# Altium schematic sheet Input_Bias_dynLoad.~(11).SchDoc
size 431 x 279 mm; Date: Not shown in title block; ApprovedBy: Not shown in title block; CheckedBy: Not shown in title block; Author: Not shown in title block; CompanyName: Not shown in title block; Engineer: Not shown in title block; Organization: Not shown in title block; Address1: Not shown in title block; Address2: Not shown in title block; Address3: Not shown in title block; Address4: Not shown in title block; DocumentNumber: 2; Revision: Use project parameter SCH_Rev; SheetNumber: 2; SheetTotal: 5; PageSetup: Record=PageOptions|CenterHorizontal=True|CenterVertical=True|PrintScale=1.00|XCorrection=1.00|YCorrection=1.00|PrintKind=0|BorderSize=5000000|LeftOffset=0|BottomOffset=0|Orientation=2|PaperLength=1000|PaperWidth=1000|Scale=100|PaperSource=15|PrintQuality=600|MediaType=1|DitherType=10|PaperKind=Letter|PrintScaleMode=1
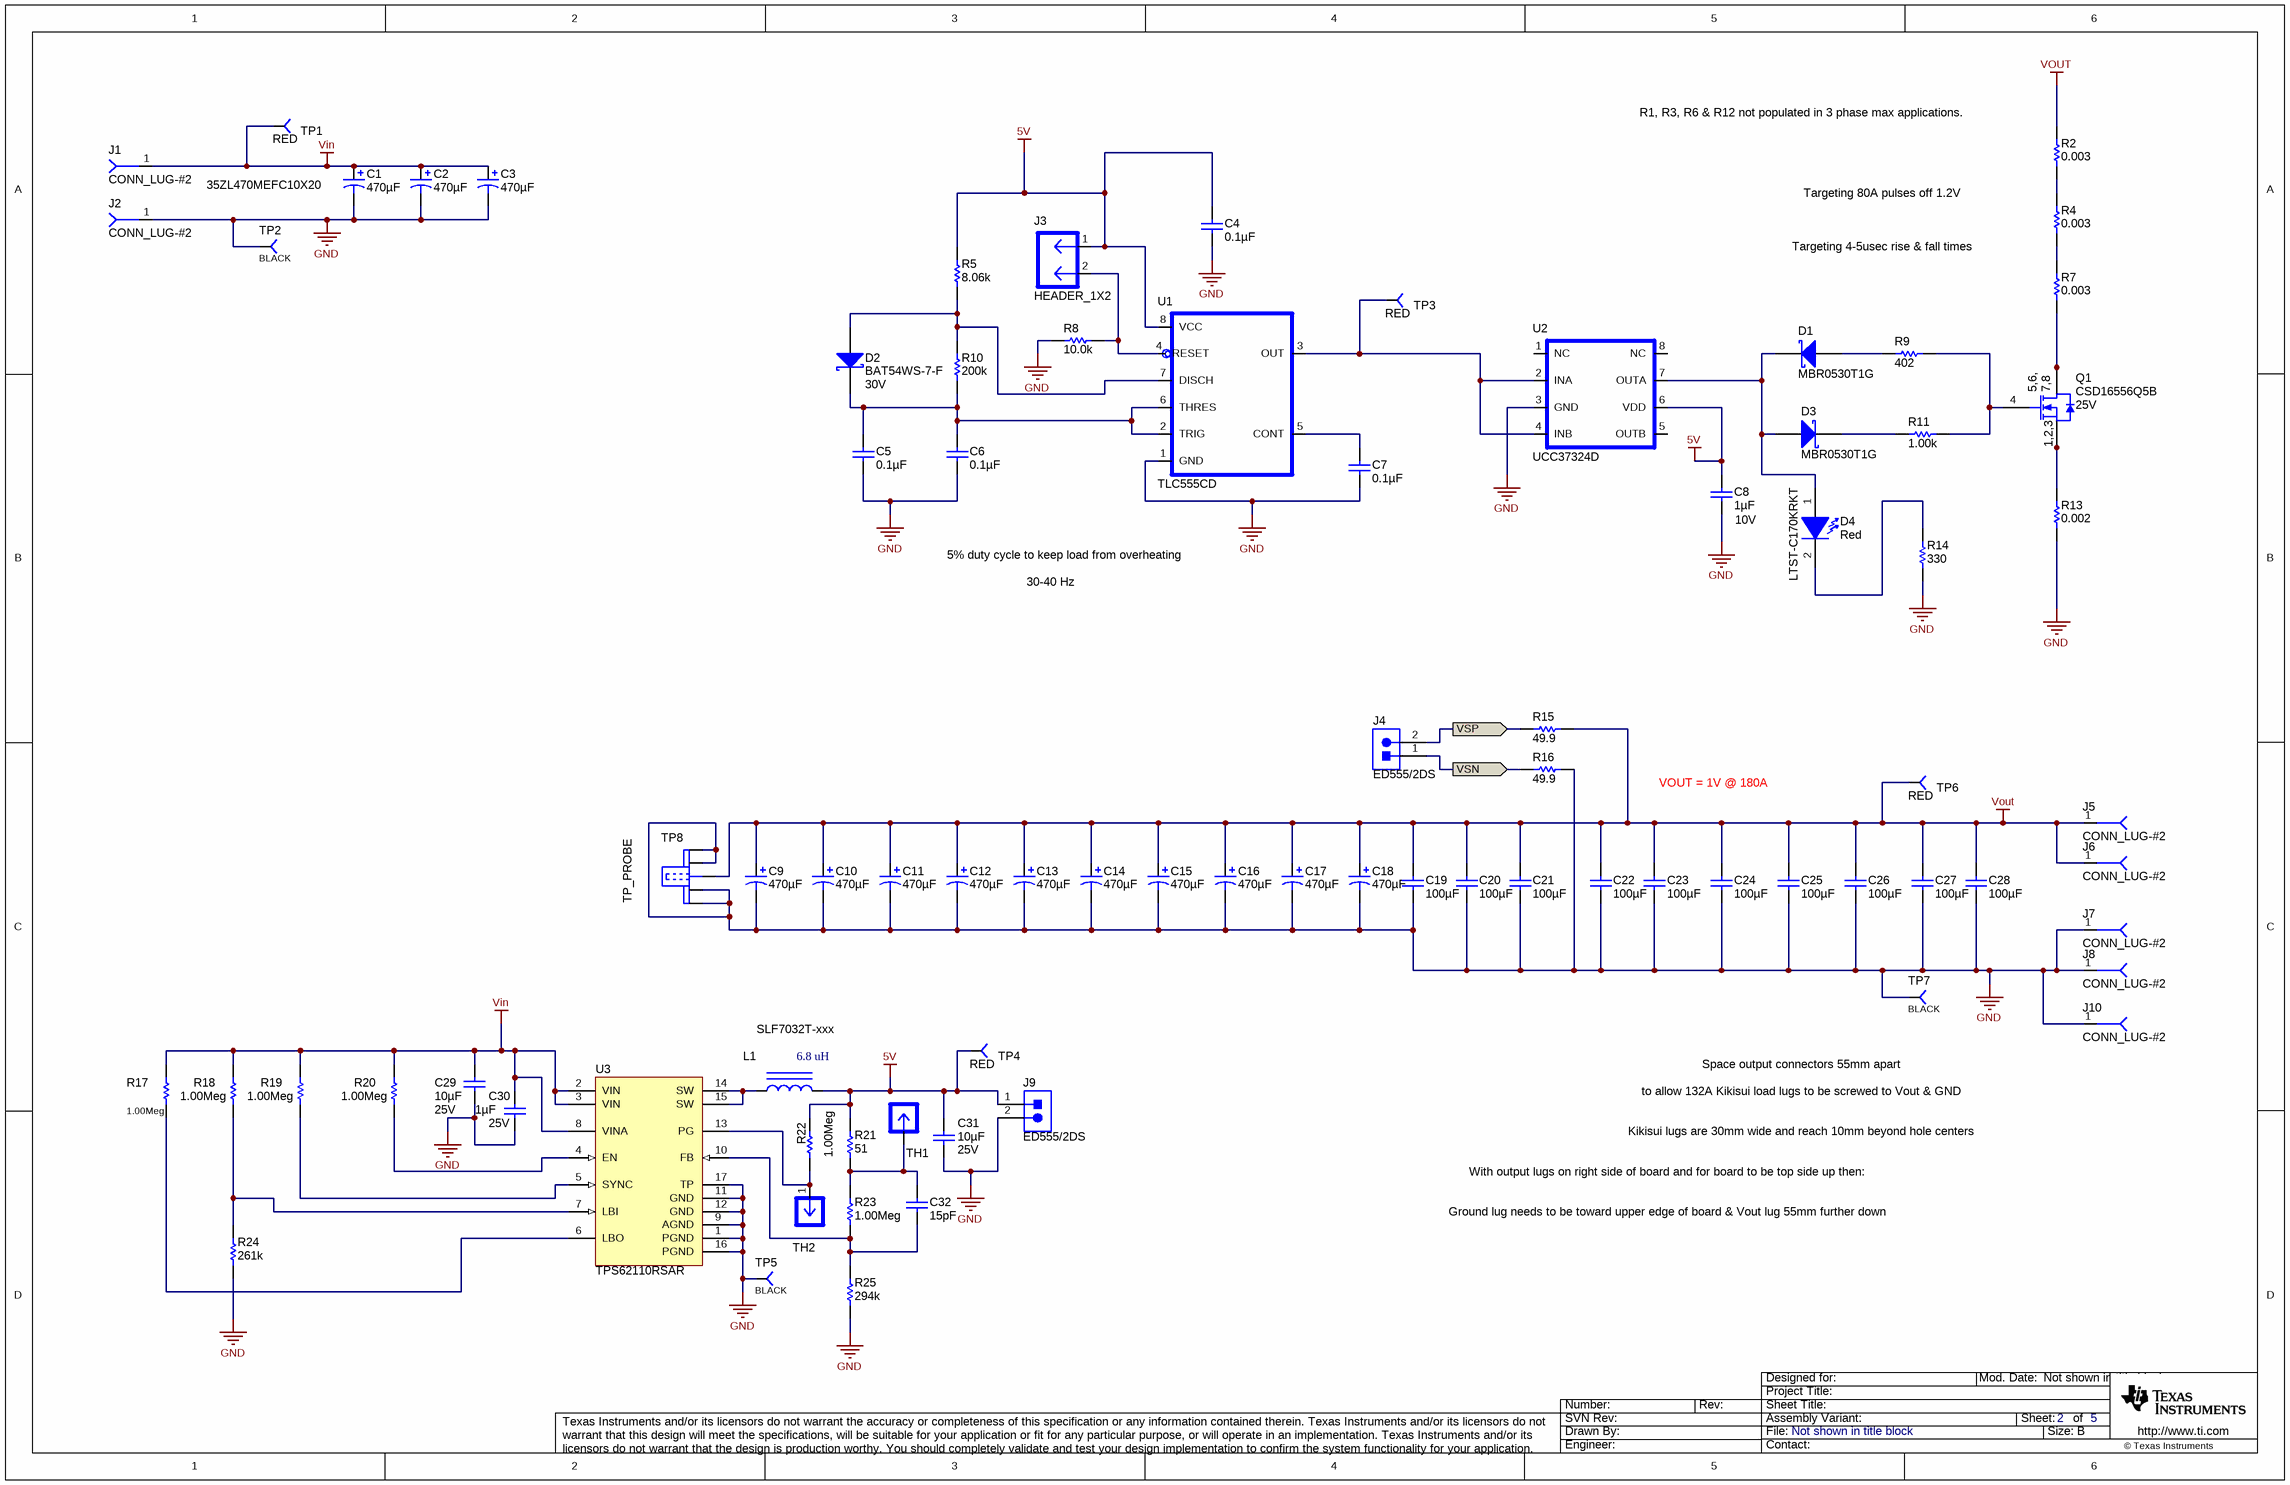
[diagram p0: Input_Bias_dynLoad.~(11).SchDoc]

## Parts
C1  ValueDisplayed: 470µF  [CAPPR5-10X20]  (hidden comment: 35ZL470MEFC10X20)
C2  ValueDisplayed: 470µF  [CAPPR5-10X20]  (hidden comment: 35ZL470MEFC10X20)
C3  ValueDisplayed: 470µF  [CAPPR5-10X20]  (hidden comment: 35ZL470MEFC10X20)
C4  ValueDisplayed: 0.1µF  [0402]  (hidden comment: C1005X7R1H104M)
C5  ValueDisplayed: 0.1µF  [0402]  (hidden comment: C1005X7R1H104M)
C6  ValueDisplayed: 0.1µF  [0402]  (hidden comment: C1005X7R1H104M)
C7  ValueDisplayed: 0.1µF  [0402]  (hidden comment: C1005X7R1H104M)
C8  ValueDisplayed: 1µF  Value2: 10V  [0402]  (hidden comment: GRM155R61A105KE15D)
C9  ValueDisplayed: 470µF  [CAPAE_SP-Cap_Standard]  (hidden comment: EEFSX0E471ER)
C10  ValueDisplayed: 470µF  [CAPAE_SP-Cap_Standard]  (hidden comment: EEFSX0E471ER)
C11  ValueDisplayed: 470µF  [CAPAE_SP-Cap_Standard]  (hidden comment: EEFSX0E471ER)
C12  ValueDisplayed: 470µF  [CAPAE_SP-Cap_Standard]  (hidden comment: EEFSX0E471ER)
C13  ValueDisplayed: 470µF  [CAPAE_SP-Cap_Standard]  (hidden comment: EEFSX0E471ER)
C14  ValueDisplayed: 470µF  [CAPAE_SP-Cap_Standard]  (hidden comment: EEFSX0E471ER)
C15  ValueDisplayed: 470µF  [CAPAE_SP-Cap_Standard]  (hidden comment: EEFSX0E471ER)
C16  ValueDisplayed: 470µF  [CAPAE_SP-Cap_Standard]  (hidden comment: EEFSX0E471ER)
C17  ValueDisplayed: 470µF  [CAPAE_SP-Cap_Standard]  (hidden comment: EEFSX0E471ER)
C18  ValueDisplayed: 470µF  [CAPAE_SP-Cap_Standard]  (hidden comment: EEFSX0E471ER)
C19  ValueDisplayed: 100µF  [1210]  (hidden comment: C1210C107M9PACTU)
C20  ValueDisplayed: 100µF  [1210]  (hidden comment: C1210C107M9PACTU)
C21  ValueDisplayed: 100µF  [1210]  (hidden comment: C1210C107M9PACTU)
C22  ValueDisplayed: 100µF  [1210]  (hidden comment: C1210C107M9PACTU)
C23  ValueDisplayed: 100µF  [1210]  (hidden comment: C1210C107M9PACTU)
C24  ValueDisplayed: 100µF  [1210]  (hidden comment: C1210C107M9PACTU)
C25  ValueDisplayed: 100µF  [1210]  (hidden comment: C1210C107M9PACTU)
C26  ValueDisplayed: 100µF  [1210]  (hidden comment: C1210C107M9PACTU)
C27  ValueDisplayed: 100µF  [1210]  (hidden comment: C1210C107M9PACTU)
C28  ValueDisplayed: 100µF  [1210]  (hidden comment: C1210C107M9PACTU)
C29  ValueDisplayed: 10µF  Value2: 25V  [1210]  (hidden comment: C3225X7R1E106M)
C30  ValueDisplayed: 1µF  Value2: 25V  [0603]  (hidden comment: GRM188R71E105KA12D)
C31  ValueDisplayed: 10µF  Value2: 25V  [1210]  (hidden comment: C3225X7R1E106M)
C32  ValueDisplayed: 15pF  [0402]  (hidden comment: GRM1555C1H150JA01D)
D1  MBR0530T1G  [SOD-123]
D2  BAT54WS-7-F  value 30V  [sod-323]
D3  MBR0530T1G  [SOD-123]
D4  LTST-C170KRKT  value Red  [LED_LTST-C170]
J1  CONN_LUG-#2  [LUG-#2]
J2  CONN_LUG-#2  [LUG-#2]
J3  HEADER_1X2  [HDR100_1X2]
J4  ED555/2DS  [TERM_BLK_ED555-2DS]
J5  CONN_LUG-#2  [LUG-#2]
J6  CONN_LUG-#2  [LUG-#2]
J7  CONN_LUG-#2  [LUG-#2]
J8  CONN_LUG-#2  [LUG-#2]
J9  ED555/2DS  [TERM_BLK_ED555-2DS]
J10  CONN_LUG-#2  [LUG-#2]
L1  SLF7032T-xxx  value 6.8 uH  [IND_SLF7032]
Q1  CSD16556Q5B  value 25V  [TRANS_NexFET_Q5B]
R2  value 0.003  [2512M]  (hidden comment: 73M1R003F)
R4  value 0.003  [2512M]  (hidden comment: 73M1R003F)
R5  value 8.06k  [0402]  (hidden comment: CRCW04028K06FKED)
R7  value 0.003  [2512M]  (hidden comment: 73M1R003F)
R8  value 10.0k  [0402]  (hidden comment: CRCW040210K0FKED)
R9  value 402  [0402]  (hidden comment: CRCW0402402RFKED)
R10  value 200k  [0402]  (hidden comment: CRCW0402200KFKED)
R11  value 1.00k  [0402]  (hidden comment: CRCW04021K00FKED)
R13  value 0.002  [2512M]  (hidden comment: CSNL2512FT2L00)
R14  value 330  [0402]  (hidden comment: CRCW0402330RJNED)
R15  value 49.9  [0402]  (hidden comment: CRCW040249R9FKED)
R16  value 49.9  [0402]  (hidden comment: CRCW040249R9FKED)
R17  value 1.00Meg  [0402]  (hidden comment: CRCW04021M00FKED)
R18  value 1.00Meg  [0402]  (hidden comment: CRCW04021M00FKED)
R19  value 1.00Meg  [0402]  (hidden comment: CRCW04021M00FKED)
R20  value 1.00Meg  [0402]  (hidden comment: CRCW04021M00FKED)
R21  value 51  [0402]  (hidden comment: CRCW040251R0JNED)
R22  value 1.00Meg  [0402]  (hidden comment: CRCW04021M00FKED)
R23  value 1.00Meg  [0402]  (hidden comment: CRCW04021M00FKED)
R24  value 261k  [0402]  (hidden comment: CRCW0402261KFKED)
R25  value 294k  [0402]  (hidden comment: CRCW0402294KFKED)
TH1  TP-15MIL  [TH-15MIL]  (value not drawn)
TH2  TP-15MIL  [TH-15MIL]  (value not drawn)
TP1  RED  [TH-40]
TP2  BLACK  [TH-40]
TP3  RED  [TH-40]
TP4  RED  [TH-40]
TP5  BLACK  [TH-40]
TP6  RED  [TH-40]
TP7  BLACK  [TH-40]
TP8  TP_PROBE  [PROBE]
U1  TLC555CD  [SO8]
U2  UCC37324D  [SO8]
U3  TPS62110RSAR  [RSA0016B]

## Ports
VSN (out), VSP (out)

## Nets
5V: C4.1 C8.1 C31.1 J3.1 J9.1 L1.2 R5.2 R21.2 R22.2 TP4.1 U1.8(VCC) U2.6(VDD)
GND: C1.2(-) C2.2(-) C3.2(-) C4.2 C5.2 C6.2 C7.2 C8.2 C9.2(-) C10.2(-) C11.2(-) C12.2(-) C13.2(-) C14.2(-) C15.2(-) C16.2(-) C17.2(-) C18.2(-) C19.2 C20.2 C21.2 C22.2 C23.2 C24.2 C25.2 C26.2 C27.2 C28.2 C29.2 C30.2 C31.2 J2.1 J7.1 J8.1 J9.2 J10.1 R8.1 R13.1 R14.1 R16.2 R24.1 R25.1 TP2.1 TP5.1 TP7.1 TP8.2(GND) TP8.3(GND) TP8.4(GND) TP8.5(GND) U1.1(GND) U2.3(GND) U3.1(PGND) U3.9(AGND) U3.11(GND) U3.12(GND) U3.16(PGND) U3.17(TP)
Vin: C1.1(+) C2.1(+) C3.1(+) C29.1 C30.1 J1.1 R17.2 R18.2 R19.1 R20.2 TP1.1 U3.2(VIN) U3.3(VIN) U3.8(VINA)
VOUT: C9.1(+) C10.1(+) C11.1(+) C12.1(+) C13.1(+) C14.1(+) C15.1(+) C16.1(+) C17.1(+) C18.1(+) C19.1 C20.1 C21.1 C22.1 C23.1 C24.1 C25.1 C26.1 C27.1 C28.1 J5.1 J6.1 R2.2 R15.2 TP6.1 TP8.1(SIGNAL)
VSN: J4.1 R16.1 ; port VSN
VSP: J4.2 R15.1 ; port VSP
NetC5_1: C5.1 C6.1 D2.1(K) R10.1 U1.2(TRIG) U1.6(THRES)
NetC7_1: C7.1 U1.5(CONT)
NetC32_1: C32.1 R21.1 R23.2 TH1.1
NetC32_2: C32.2 R23.1 R25.2 U3.10(FB)
NetD1_1: D1.1(K) D3.2(A) D4.1(A) U2.7(OUTA)
NetD1_2: D1.2(A) R9.1
NetD2_2: D2.2(A) R5.1 R10.2 U1.7(DISCH)
NetD3_1: D3.1(K) R11.1
NetD4_2: D4.2(K) R14.2
NetJ3_2: J3.2 R8.2 U1.4(RESET)
NetL1_1: L1.1 U3.14(SW) U3.15(SW)
NetQ1_1: Q1.1(S) Q1.2(S) Q1.3(S) R13.2
NetQ1_4: Q1.4(G) R9.2 R11.2
NetQ1_5: Q1.5(D) Q1.6(D) Q1.7(D) Q1.8(D) R7.1
NetR2_1: R2.1 R4.2
NetR4_1: R4.1 R7.2
NetR17_1: R17.1 U3.6(LBO)
NetR18_1: R18.1 R24.2 U3.7(LBI)
NetR19_2: R19.2 U3.5(SYNC)
NetR20_1: R20.1 U3.4(EN)
NetR22_1: R22.1 TH2.1 U3.13(PG)
NetTP3_1: TP3.1 U1.3(OUT) U2.2(INA) U2.4(INB)

Not connected (* = marked no-connect by the designer): U2 1(NC) 5(OUTB) 8(NC)

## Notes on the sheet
- R1, R3, R6 & R12 not populated in 3 phase max applications.
- Targeting 80A pulses off 1.2V
- Targeting 4-5usec rise & fall times
- 5% duty cycle to keep load from overheating
- 30-40 Hz
- VOUT = 1V @ 180A
- Space output connectors 55mm apart
- to allow 132A Kikisui load lugs to be screwed to Vout & GND
- With output lugs on right side of board and for board to be top side up then:
- Kikisui lugs are 30mm wide and reach 10mm beyond hole centers
- Ground lug needs to be toward upper edge of board & Vout lug 55mm further down

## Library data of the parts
C1-C3 = 35ZL470MEFC10X20: CAP, AL, 470uF, 35V, +/-20%, TH; Manufacturer: Rubycon; Polarized: Y; CompType: Capacitor; U/M: EA; Cap_F: 0.00047; Tolerance_%: 20; Value1: Unknown; VDC_V: 35; TaMin_C: -40; TaMax_C: 105; Cap_Case: 10x20
C4-C7 = C1005X7R1H104M: CAP, CERM, 0.1uF, 50V, +/-20%, X7R, 0402; Manufacturer: TDK; Polarized: N; CompType: Capacitor; U/M: EA; Cap_F: 0.0000001; Tolerance_%: 20; Value1: Unknown; VDC_V: 50; TempCo: C0G/NP0; TaMin_C: -55; TaMax_C: 125
C8 = GRM155R61A105KE15D: CAP, CERM, 1uF, 10V, +/-10%, X5R, 0402; Manufacturer: MuRata; Polarized: N; CompType: Capacitor; U/M: EA; Cap_F: 0.000001; Tolerance_%: 10; Value1: Unknown; TaMin_C: -55; TaMax_C: 85
C9-C18 = EEFSX0E471ER: CAP, AL, 470uF, 2.5V, +/-20%, 9 ohm, SMD; Manufacturer: Panasonic; Polarized: Y; CompType: Capacitor; U/M: EA; Cap_F: 0.00047; Tolerance_%: 20; Value1: 9 ohm; VDC_V: 2.5; ESR_Ohm: 9; IRMS_A: 3; TaMin_C: -40; TaMax_C: 105
C19-C28 = C1210C107M9PACTU: CAP, CERM, 100uF, 6.3V, +/-20%, X5R, 1210; Manufacturer: Kemet; Polarized: N; CompType: Capacitor; U/M: EA; Cap_F: 0.0001; Tolerance_%: 20; Value1: Unknown; VDC_V: 6.3; TaMin_C: -55; TaMax_C: 85
C29 C31 = C3225X7R1E106M: CAP, CERM, 10uF, 25V, +/-20%, X7R, 1210; Manufacturer: TDK; Polarized: N; CompType: Capacitor; U/M: EA; Cap_F: 0.00001; Tolerance_%: 20; ESR_Ohm: 0.0027; Value1: 0.0027 ohm; VDC_V: 25; IRMS_A: 3; TaMin_C: -55; TaMax_C: 125
C30 = GRM188R71E105KA12D: CAP, CERM, 1uF, 25V, +/-10%, X7R, 0603; Manufacturer: MuRata; Polarized: N; CompType: Capacitor; U/M: EA; Cap_F: 0.000001; Tolerance_%: 10; Value1: Unknown; VDC_V: 25; TaMin_C: -55; TaMax_C: 125
C32 = GRM1555C1H150JA01D: CAP, CERM, 15pF, 50V, +/-5%, C0G/NP0, 0402; Manufacturer: MuRata; Polarized: N; CompType: Capacitor; U/M: EA; Cap_F: 0.000000000015; Tolerance_%: 5; Value1: Unknown; VDC_V: 50; TaMin_C: -55; TaMax_C: 125
D1 D3 = MBR0530T1G: Diode, Schottky, 30V, 0.5A, SOD-123; Manufacturer: ON Semiconductor; U/M: EA; Vf_V: 0.43; Value2: 0.43V; Io_A: 0.5; Vr_V: 30; TJmax_C: 125; RJC_CperW: 150
D2 = BAT54WS-7-F: Diode, Schottky, 30V, 0.2A, SOD-323; Manufacturer: Diodes Inc.; U/M: EA; Vf_V: 0.7; Value2: 0.7V; Io_A: 0.2; Vr_V: 30; TJmax_C: 125
D4 = LTST-C170KRKT: LED, Red, SMD; Manufacturer: Lite-On; Type: AlInGaP; Vf_V: 2; Value2: 2V; Io_A: 20; Value1: W; U/M: EA
J1 J2 J5-J8 J10 = CONN_LUG-#2: Lug, Solderless, #2 - #8 AWG, 1/4", Copper; Manufacturer: ILSCO; PartNumber: GSLU-70; area: 960000; Value: GSLU-70
J3 = HEADER_1X2: Header, Male 2-pin, 100mil spacing,; Manufacturer: Sullins; PartNumber: PEC02SAAN; area: 20000; Value: PEC02SAAN
J4 J9 = ED555/2DS: Terminal Block, 6A, 3.5mm Pitch, 2-Pos, TH; Manufacturer: On-Shore Technology; SymbolCreator: a0412235; CompType: Connector; U/M: EA
L1 = IND_SLF7032T-XXX: Inductor, SMT, yyA, zzmilliohm; Manufacturer: TDK; Area: 114,138
Q1 = CSD16556Q5B: MOSFET, N-CH, 25V, 40A, SON 5x6mm; Manufacturer: Texas Instruments; Alternate Manufacturer: None; U/M: EA; ChType: N; VdsMax_V: 25; Value1: 0.0012 ohm; Rdson45_Ohm: 0.0012; Value2: 36 nC; QgTyp_nC: 36; Vgs_V: 20; IdsMax_A: 40
R2 R4 R7 = 73M1R003F: RES, 0.003 ohm, 1%, 1W, 2512; Manufacturer: CTS Resistor; CompType: Resistor; Value_Code: R003; Tolerance_%: 1; TempCo: 300 ppm/C; EIA_Code: E96; U/M: EA
R5 = CRCW04028K06FKED: RES, 8.06k ohm, 1%, 0.063W, 0402; Manufacturer: Vishay-Dale; CompType: Resistor; Res_ohm: 8060; Value_Code: 8k06; Tolerance_%: 1; Power_W: 0.063; VDC_V: 50; TempCo: 100 ppm/C; EIA_Code: E96; U/M: EA
R8 = CRCW040210K0FKED: RES, 10.0k ohm, 1%, 0.063W, 0402; Manufacturer: Vishay-Dale; CompType: Resistor; Res_ohm: 10000; Value_Code: 10k0; Tolerance_%: 1; Power_W: 0.063; VDC_V: 50; TempCo: 100 ppm/C; EIA_Code: E96; U/M: EA
R9 = CRCW0402402RFKED: RES, 402 ohm, 1%, 0.063W, 0402; Manufacturer: Vishay-Dale; CompType: Resistor; Value_Code: 402R; Tolerance_%: 1; Power_W: 0.063; VDC_V: 50; TempCo: 100 ppm/C; EIA_Code: E96; U/M: EA
R10 = CRCW0402200KFKED: RES, 200k ohm, 1%, 0.063W, 0402; Manufacturer: Vishay-Dale; CompType: Resistor; Res_ohm: 200000; Tolerance_%: 1; Power_W: 0.063; VDC_V: 50; TempCo: 100 ppm/C; EIA_Code: E96; U/M: EA
R11 = CRCW04021K00FKED: RES, 1.00k ohm, 1%, 0.063W, 0402; Manufacturer: Vishay-Dale; CompType: Resistor; Res_ohm: 1000; Value_Code: 1k00; Tolerance_%: 1; Power_W: 0.063; VDC_V: 50; TempCo: 100 ppm/C; EIA_Code: E96; U/M: EA
R13 = CSNL2512FT2L00: RES, 0.002 ohm, 1%, 2W, 2512; Manufacturer: Stackpole Electronics Inc; CompType: Resistor; Value_Code: R002; Tolerance_%: 1; Power_W: 2; VDC_V: 200; TempCo: 50 ppm/C; U/M: EA
R14 = CRCW0402330RJNED: RES, 330 ohm, 5%, 0.063W, 0402; Manufacturer: Vishay-Dale; CompType: Resistor; Value_Code: 330R; Tolerance_%: 5; Power_W: 0.063; VDC_V: 50; TempCo: 200 ppm/C; EIA_Code: E24; U/M: EA
R15 R16 = CRCW040249R9FKED: RES, 49.9 ohm, 1%, 0.063W, 0402; Manufacturer: Vishay-Dale; CompType: Resistor; Value_Code: 49R9; Tolerance_%: 1; Power_W: 0.063; VDC_V: 50; TempCo: 100 ppm/C; EIA_Code: E96; U/M: EA
R17-R20 R22 R23 = CRCW04021M00FKED: RES, 1.00Meg ohm, 1%, 0.063W, 0402; Manufacturer: Vishay-Dale; CompType: Resistor; Res_ohm: 1000000; Value_Code: 1M00; Tolerance_%: 1; Power_W: 0.063; VDC_V: 50; TempCo: 100 ppm/C; EIA_Code: E96; U/M: EA
R21 = CRCW040251R0JNED: RES, 51 ohm, 5%, 0.063W, 0402; Manufacturer: Vishay-Dale; CompType: Resistor; Value_Code: 51R0; Tolerance_%: 5; Power_W: 0.063; VDC_V: 50; TempCo: 200 ppm/C; EIA_Code: E24; U/M: EA
R24 = CRCW0402261KFKED: RES, 261k ohm, 1%, 0.063W, 0402; Manufacturer: Vishay-Dale; CompType: Resistor; Res_ohm: 261000; Tolerance_%: 1; Power_W: 0.063; VDC_V: 50; TempCo: 100 ppm/C; EIA_Code: E96; U/M: EA
R25 = CRCW0402294KFKED: RES, 294k ohm, 1%, 0.063W, 0402; Manufacturer: Vishay-Dale; CompType: Resistor; Res_ohm: 294000; Tolerance_%: 1; Power_W: 0.063; VDC_V: 50; TempCo: 100 ppm/C; EIA_Code: E96; U/M: EA
TH1 TH2 = TP-15MIL: Thru Hole, 15 mil, plated
TP1 TP3 TP4 TP6 = TP-5000-RED: Test Point,  Red, Thru Hole Color Keyed; Manufacturer: Keystone; PartNumber: 5000; area: 10.000; Value: 5000
TP2 TP5 TP7 = TP-5001-BLACK: Test Point,  Black, Thru Hole Color Keyed; Manufacturer: Keystone; PartNumber: 5001; area: 10.000; Value: 5001
TP8 = TP_PROBE: Adaptor, 3.5-mm probe clip (or 131-5031-00); Manufacturer: Tektronix; PartNumber: 131-4244-00; Value: 131-4244-00
U1 = TLC555CD: IC, Timer, Low-Power CMOS; Manufacturer: TI; Alternate Manufacturer: None; Area: 75900
U2 = UCC3732XD: IC, Dual  4-A High Speed Low-Side Power MOSFET Drivers; Manufacturer: TI; Alternate Manufacturer: None; Area: 75900
U3 = TPS62110RSAR: Buck Adjustable Regulator with 3.1 to 17 V Input and 1.2 to 16 V Output, -40 to 85 degC, 16-Pin QFN (RSA), Green (RoHS & no Sb/Br); Manufacturer: Texas Instruments; Alternate Manufacturer: None; Alternate PartNumber: Equivalent; Duty Cycle(Max)(%): 100; Iout(Max)(A): 1.5; Iq(Typ)(mA): 0.02; Rating: Catalog; Regulated Outputs(#): 1; SubFamily: Step-Down Regulator; Switch Current Limit(Typ)(A): 2.4; Synchronous Rectification: TRUE; Vin(Max)(V): 17; Vin(Min)(V): 3.1; Vout(Max)(V): 16; Vout(Min)(V): 1.2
